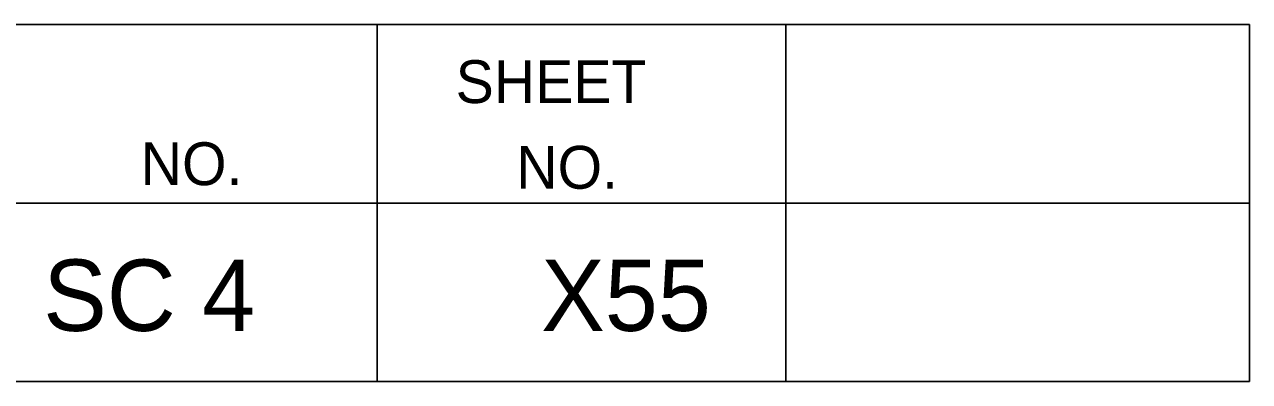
# Model space of a CAD drawing. Extents: x 1000 to 1162, y 999 to 8520.
# Drawn here: x 1152.97 to 1161.56, y 7310.05 to 7312.55 of the extents above; entities that cross this region are included whole.
import ezdxf

# ---------------------------------------------------------------- set-up
doc = ezdxf.new("R2010")
doc.units = 0
doc.layers.add('Level 20', color=7, linetype='Continuous')
doc.layers.add('Level 3', color=7, linetype='Continuous')

msp = doc.modelspace()

# ---------------------------------------------------------------- linework, layer by layer
at = {"layer": 'Level 3'}
for p, q in [((1133.055, 7312.5458), (1161.555, 7312.5458)), ((1133.055, 7312.5458), (1161.555, 7312.5458)), ((1133.055, 7312.5458), (1161.555, 7312.5458)), ((1133.055, 7312.5458), (1161.555, 7312.5458)), ((1133.055, 7312.5458), (1161.555, 7312.5458)), ((1133.055, 7312.5458), (1161.555, 7312.5458)), ((1133.055, 7312.5458), (1161.555, 7312.5458)), ((1133.055, 7312.5458), (1161.555, 7312.5458)), ((1133.055, 7312.5458), (1161.555, 7312.5458)), ((1133.055, 7312.5458), (1161.555, 7312.5458)), ((1133.055, 7312.5458), (1161.555, 7312.5458)), ((1133.055, 7312.5458), (1161.555, 7312.5458)), ((1133.055, 7312.5458), (1161.555, 7312.5458)), ((1133.055, 7312.5458), (1161.555, 7312.5458)), ((1133.055, 7312.5458), (1161.555, 7312.5458)), ((1133.055, 7312.5458), (1161.555, 7312.5458)), ((1133.055, 7312.5458), (1161.555, 7312.5458)), ((1133.055, 7312.5458), (1161.555, 7312.5458)), ((1133.055, 7312.5458), (1161.555, 7312.5458)), ((1133.055, 7312.5458), (1161.555, 7312.5458)), ((1133.055, 7312.5458), (1161.555, 7312.5458)), ((1133.055, 7312.5458), (1161.555, 7312.5458)), ((1133.055, 7312.5458), (1161.555, 7312.5458)), ((1133.055, 7312.5458), (1161.555, 7312.5458)), ((1133.055, 7312.5458), (1161.555, 7312.5458)), ((1133.055, 7312.5458), (1161.555, 7312.5458)), ((1133.055, 7312.5458), (1161.555, 7312.5458)), ((1133.055, 7312.5458), (1161.555, 7312.5458)), ((1133.055, 7312.5458), (1161.555, 7312.5458)), ((1133.055, 7312.5458), (1161.555, 7312.5458)), ((1133.055, 7312.5458), (1161.555, 7312.5458)), ((1133.055, 7312.5458), (1161.555, 7312.5458)), ((1133.055, 7312.5458), (1161.555, 7312.5458)), ((1133.055, 7312.5458), (1161.555, 7312.5458)), ((1133.055, 7312.5458), (1161.555, 7312.5458)), ((1133.055, 7312.5458), (1161.555, 7312.5458)), ((1133.055, 7312.5458), (1161.555, 7312.5458)), ((1133.055, 7312.5458), (1161.555, 7312.5458)), ((1133.055, 7312.5458), (1161.555, 7312.5458)), ((1133.055, 7312.5458), (1161.555, 7312.5458)), ((1133.055, 7312.5458), (1161.555, 7312.5458)), ((1133.055, 7312.5458), (1161.555, 7312.5458)), ((1133.055, 7312.5458), (1161.555, 7312.5458)), ((1133.055, 7312.5458), (1161.555, 7312.5458)), ((1133.055, 7312.5458), (1161.555, 7312.5458)), ((1133.055, 7312.5458), (1161.555, 7312.5458)), ((1133.055, 7312.5458), (1161.555, 7312.5458)), ((1133.055, 7312.5458), (1161.555, 7312.5458)), ((1133.055, 7312.5458), (1161.555, 7312.5458)), ((1133.055, 7312.5458), (1161.555, 7312.5458)), ((1133.055, 7312.5458), (1161.555, 7312.5458)), ((1133.055, 7312.5458), (1161.555, 7312.5458)), ((1133.055, 7312.5458), (1161.555, 7312.5458)), ((1155.44, 7312.5458), (1155.44, 7310.0458)), ((1155.44, 7312.5458), (1155.44, 7310.0458)), ((1155.44, 7312.5458), (1155.44, 7310.0458)), ((1155.44, 7312.5458), (1155.44, 7310.0458)), ((1155.44, 7312.5458), (1155.44, 7310.0458)), ((1155.44, 7312.5458), (1155.44, 7310.0458)), ((1155.44, 7312.5458), (1155.44, 7310.0458)), ((1155.44, 7312.5458), (1155.44, 7310.0458)), ((1155.44, 7312.5458), (1155.44, 7310.0458)), ((1155.44, 7312.5458), (1155.44, 7310.0458)), ((1155.44, 7312.5458), (1155.44, 7310.0458)), ((1155.44, 7312.5458), (1155.44, 7310.0458)), ((1155.44, 7312.5458), (1155.44, 7310.0458)), ((1155.44, 7312.5458), (1155.44, 7310.0458)), ((1155.44, 7312.5458), (1155.44, 7310.0458)), ((1155.44, 7312.5458), (1155.44, 7310.0458)), ((1155.44, 7312.5458), (1155.44, 7310.0458)), ((1155.44, 7312.5458), (1155.44, 7310.0458)), ((1155.44, 7312.5458), (1155.44, 7310.0458)), ((1155.44, 7312.5458), (1155.44, 7310.0458)), ((1155.44, 7312.5458), (1155.44, 7310.0458)), ((1155.44, 7312.5458), (1155.44, 7310.0458)), ((1155.44, 7312.5458), (1155.44, 7310.0458)), ((1155.44, 7312.5458), (1155.44, 7310.0458)), ((1155.44, 7312.5458), (1155.44, 7310.0458)), ((1155.44, 7312.5458), (1155.44, 7310.0458)), ((1155.44, 7312.5458), (1155.44, 7310.0458)), ((1155.44, 7312.5458), (1155.44, 7310.0458)), ((1155.44, 7312.5458), (1155.44, 7310.0458)), ((1155.44, 7312.5458), (1155.44, 7310.0458)), ((1155.44, 7312.5458), (1155.44, 7310.0458)), ((1155.44, 7312.5458), (1155.44, 7310.0458)), ((1155.44, 7312.5458), (1155.44, 7310.0458)), ((1155.44, 7312.5458), (1155.44, 7310.0458)), ((1155.44, 7312.5458), (1155.44, 7310.0458)), ((1155.44, 7312.5458), (1155.44, 7310.0458)), ((1155.44, 7312.5458), (1155.44, 7310.0458)), ((1155.44, 7312.5458), (1155.44, 7310.0458)), ((1155.44, 7312.5458), (1155.44, 7310.0458)), ((1155.44, 7312.5458), (1155.44, 7310.0458)), ((1155.44, 7312.5458), (1155.44, 7310.0458)), ((1155.44, 7312.5458), (1155.44, 7310.0458)), ((1155.44, 7312.5458), (1155.44, 7310.0458)), ((1155.44, 7312.5458), (1155.44, 7310.0458)), ((1155.44, 7312.5458), (1155.44, 7310.0458)), ((1155.44, 7312.5458), (1155.44, 7310.0458)), ((1155.44, 7312.5458), (1155.44, 7310.0458)), ((1155.44, 7312.5458), (1155.44, 7310.0458)), ((1155.44, 7312.5458), (1155.44, 7310.0458)), ((1155.44, 7312.5458), (1155.44, 7310.0458)), ((1155.44, 7312.5458), (1155.44, 7310.0458)), ((1155.44, 7312.5458), (1155.44, 7310.0458)), ((1155.44, 7312.5458), (1155.44, 7310.0458)), ((1158.305, 7312.5458), (1158.305, 7310.0458)), ((1158.305, 7312.5458), (1158.305, 7310.0458)), ((1158.305, 7312.5458), (1158.305, 7310.0458)), ((1158.305, 7312.5458), (1158.305, 7310.0458)), ((1158.305, 7312.5458), (1158.305, 7310.0458)), ((1158.305, 7312.5458), (1158.305, 7310.0458)), ((1158.305, 7312.5458), (1158.305, 7310.0458)), ((1158.305, 7312.5458), (1158.305, 7310.0458)), ((1158.305, 7312.5458), (1158.305, 7310.0458)), ((1158.305, 7312.5458), (1158.305, 7310.0458)), ((1158.305, 7312.5458), (1158.305, 7310.0458)), ((1158.305, 7312.5458), (1158.305, 7310.0458)), ((1158.305, 7312.5458), (1158.305, 7310.0458)), ((1158.305, 7312.5458), (1158.305, 7310.0458)), ((1158.305, 7312.5458), (1158.305, 7310.0458)), ((1158.305, 7312.5458), (1158.305, 7310.0458)), ((1158.305, 7312.5458), (1158.305, 7310.0458)), ((1158.305, 7312.5458), (1158.305, 7310.0458)), ((1158.305, 7312.5458), (1158.305, 7310.0458)), ((1158.305, 7312.5458), (1158.305, 7310.0458)), ((1158.305, 7312.5458), (1158.305, 7310.0458)), ((1158.305, 7312.5458), (1158.305, 7310.0458)), ((1158.305, 7312.5458), (1158.305, 7310.0458)), ((1158.305, 7312.5458), (1158.305, 7310.0458)), ((1158.305, 7312.5458), (1158.305, 7310.0458)), ((1158.305, 7312.5458), (1158.305, 7310.0458)), ((1158.305, 7312.5458), (1158.305, 7310.0458)), ((1158.305, 7312.5458), (1158.305, 7310.0458)), ((1158.305, 7312.5458), (1158.305, 7310.0458)), ((1158.305, 7312.5458), (1158.305, 7310.0458)), ((1158.305, 7312.5458), (1158.305, 7310.0458)), ((1158.305, 7312.5458), (1158.305, 7310.0458)), ((1158.305, 7312.5458), (1158.305, 7310.0458)), ((1158.305, 7312.5458), (1158.305, 7310.0458)), ((1158.305, 7312.5458), (1158.305, 7310.0458)), ((1158.305, 7312.5458), (1158.305, 7310.0458)), ((1158.305, 7312.5458), (1158.305, 7310.0458)), ((1158.305, 7312.5458), (1158.305, 7310.0458)), ((1158.305, 7312.5458), (1158.305, 7310.0458)), ((1158.305, 7312.5458), (1158.305, 7310.0458)), ((1158.305, 7312.5458), (1158.305, 7310.0458)), ((1158.305, 7312.5458), (1158.305, 7310.0458)), ((1158.305, 7312.5458), (1158.305, 7310.0458)), ((1158.305, 7312.5458), (1158.305, 7310.0458)), ((1158.305, 7312.5458), (1158.305, 7310.0458)), ((1158.305, 7312.5458), (1158.305, 7310.0458)), ((1158.305, 7312.5458), (1158.305, 7310.0458)), ((1158.305, 7312.5458), (1158.305, 7310.0458)), ((1158.305, 7312.5458), (1158.305, 7310.0458)), ((1158.305, 7312.5458), (1158.305, 7310.0458)), ((1158.305, 7312.5458), (1158.305, 7310.0458)), ((1158.305, 7312.5458), (1158.305, 7310.0458)), ((1158.305, 7312.5458), (1158.305, 7310.0458)), ((1161.555, 7312.5458), (1161.555, 7310.0458)), ((1161.555, 7312.5458), (1161.555, 7310.0458)), ((1161.555, 7312.5458), (1161.555, 7310.0458)), ((1161.555, 7312.5458), (1161.555, 7310.0458)), ((1161.555, 7312.5458), (1161.555, 7310.0458)), ((1161.555, 7312.5458), (1161.555, 7310.0458)), ((1161.555, 7312.5458), (1161.555, 7310.0458)), ((1161.555, 7312.5458), (1161.555, 7310.0458)), ((1161.555, 7312.5458), (1161.555, 7310.0458)), ((1161.555, 7312.5458), (1161.555, 7310.0458)), ((1161.555, 7312.5458), (1161.555, 7310.0458)), ((1161.555, 7312.5458), (1161.555, 7310.0458)), ((1161.555, 7312.5458), (1161.555, 7310.0458)), ((1161.555, 7312.5458), (1161.555, 7310.0458)), ((1161.555, 7312.5458), (1161.555, 7310.0458)), ((1161.555, 7312.5458), (1161.555, 7310.0458)), ((1161.555, 7312.5458), (1161.555, 7310.0458)), ((1161.555, 7312.5458), (1161.555, 7310.0458)), ((1161.555, 7312.5458), (1161.555, 7310.0458)), ((1161.555, 7312.5458), (1161.555, 7310.0458)), ((1161.555, 7312.5458), (1161.555, 7310.0458)), ((1161.555, 7312.5458), (1161.555, 7310.0458)), ((1161.555, 7312.5458), (1161.555, 7310.0458)), ((1161.555, 7312.5458), (1161.555, 7310.0458)), ((1161.555, 7312.5458), (1161.555, 7310.0458)), ((1161.555, 7312.5458), (1161.555, 7310.0458)), ((1161.555, 7312.5458), (1161.555, 7310.0458)), ((1161.555, 7312.5458), (1161.555, 7310.0458)), ((1161.555, 7312.5458), (1161.555, 7310.0458)), ((1161.555, 7312.5458), (1161.555, 7310.0458)), ((1161.555, 7312.5458), (1161.555, 7310.0458)), ((1161.555, 7312.5458), (1161.555, 7310.0458)), ((1161.555, 7312.5458), (1161.555, 7310.0458)), ((1161.555, 7312.5458), (1161.555, 7310.0458)), ((1161.555, 7312.5458), (1161.555, 7310.0458)), ((1161.555, 7312.5458), (1161.555, 7310.0458)), ((1161.555, 7312.5458), (1161.555, 7310.0458)), ((1161.555, 7312.5458), (1161.555, 7310.0458)), ((1161.555, 7312.5458), (1161.555, 7310.0458)), ((1161.555, 7312.5458), (1161.555, 7310.0458)), ((1161.555, 7312.5458), (1161.555, 7310.0458)), ((1161.555, 7312.5458), (1161.555, 7310.0458)), ((1161.555, 7312.5458), (1161.555, 7310.0458)), ((1161.555, 7312.5458), (1161.555, 7310.0458)), ((1161.555, 7312.5458), (1161.555, 7310.0458)), ((1161.555, 7312.5458), (1161.555, 7310.0458)), ((1161.555, 7312.5458), (1161.555, 7310.0458)), ((1161.555, 7312.5458), (1161.555, 7310.0458)), ((1161.555, 7312.5458), (1161.555, 7310.0458)), ((1161.555, 7312.5458), (1161.555, 7310.0458)), ((1161.555, 7312.5458), (1161.555, 7310.0458)), ((1161.555, 7312.5458), (1161.555, 7310.0458)), ((1161.555, 7312.5458), (1161.555, 7310.0458)), ((1133.055, 7311.2958), (1161.555, 7311.2958)), ((1133.055, 7311.2958), (1161.555, 7311.2958)), ((1133.055, 7311.2958), (1161.555, 7311.2958)), ((1133.055, 7311.2958), (1161.555, 7311.2958)), ((1133.055, 7311.2958), (1161.555, 7311.2958)), ((1133.055, 7311.2958), (1161.555, 7311.2958)), ((1133.055, 7311.2958), (1161.555, 7311.2958)), ((1133.055, 7311.2958), (1161.555, 7311.2958)), ((1133.055, 7311.2958), (1161.555, 7311.2958)), ((1133.055, 7311.2958), (1161.555, 7311.2958)), ((1133.055, 7311.2958), (1161.555, 7311.2958)), ((1133.055, 7311.2958), (1161.555, 7311.2958)), ((1133.055, 7311.2958), (1161.555, 7311.2958)), ((1133.055, 7311.2958), (1161.555, 7311.2958)), ((1133.055, 7311.2958), (1161.555, 7311.2958)), ((1133.055, 7311.2958), (1161.555, 7311.2958)), ((1133.055, 7311.2958), (1161.555, 7311.2958)), ((1133.055, 7311.2958), (1161.555, 7311.2958)), ((1133.055, 7311.2958), (1161.555, 7311.2958)), ((1133.055, 7311.2958), (1161.555, 7311.2958)), ((1133.055, 7311.2958), (1161.555, 7311.2958)), ((1133.055, 7311.2958), (1161.555, 7311.2958)), ((1133.055, 7311.2958), (1161.555, 7311.2958)), ((1133.055, 7311.2958), (1161.555, 7311.2958)), ((1133.055, 7311.2958), (1161.555, 7311.2958)), ((1133.055, 7311.2958), (1161.555, 7311.2958)), ((1133.055, 7311.2958), (1161.555, 7311.2958)), ((1133.055, 7311.2958), (1161.555, 7311.2958)), ((1133.055, 7311.2958), (1161.555, 7311.2958)), ((1133.055, 7311.2958), (1161.555, 7311.2958)), ((1133.055, 7311.2958), (1161.555, 7311.2958)), ((1133.055, 7311.2958), (1161.555, 7311.2958)), ((1133.055, 7311.2958), (1161.555, 7311.2958)), ((1133.055, 7311.2958), (1161.555, 7311.2958)), ((1133.055, 7311.2958), (1161.555, 7311.2958)), ((1133.055, 7311.2958), (1161.555, 7311.2958)), ((1133.055, 7311.2958), (1161.555, 7311.2958)), ((1133.055, 7311.2958), (1161.555, 7311.2958)), ((1133.055, 7311.2958), (1161.555, 7311.2958)), ((1133.055, 7311.2958), (1161.555, 7311.2958)), ((1133.055, 7311.2958), (1161.555, 7311.2958)), ((1133.055, 7311.2958), (1161.555, 7311.2958)), ((1133.055, 7311.2958), (1161.555, 7311.2958)), ((1133.055, 7311.2958), (1161.555, 7311.2958)), ((1133.055, 7311.2958), (1161.555, 7311.2958)), ((1133.055, 7311.2958), (1161.555, 7311.2958)), ((1133.055, 7311.2958), (1161.555, 7311.2958)), ((1133.055, 7311.2958), (1161.555, 7311.2958)), ((1133.055, 7311.2958), (1161.555, 7311.2958)), ((1133.055, 7311.2958), (1161.555, 7311.2958)), ((1133.055, 7311.2958), (1161.555, 7311.2958)), ((1133.055, 7311.2958), (1161.555, 7311.2958)), ((1133.055, 7311.2958), (1161.555, 7311.2958)), ((1133.055, 7310.0458), (1161.555, 7310.0458)), ((1133.055, 7310.0458), (1161.555, 7310.0458)), ((1133.055, 7310.0458), (1161.555, 7310.0458)), ((1133.055, 7310.0458), (1161.555, 7310.0458)), ((1133.055, 7310.0458), (1161.555, 7310.0458)), ((1133.055, 7310.0458), (1161.555, 7310.0458)), ((1133.055, 7310.0458), (1161.555, 7310.0458)), ((1133.055, 7310.0458), (1161.555, 7310.0458)), ((1133.055, 7310.0458), (1161.555, 7310.0458)), ((1133.055, 7310.0458), (1161.555, 7310.0458)), ((1133.055, 7310.0458), (1161.555, 7310.0458)), ((1133.055, 7310.0458), (1161.555, 7310.0458)), ((1133.055, 7310.0458), (1161.555, 7310.0458)), ((1133.055, 7310.0458), (1161.555, 7310.0458)), ((1133.055, 7310.0458), (1161.555, 7310.0458)), ((1133.055, 7310.0458), (1161.555, 7310.0458)), ((1133.055, 7310.0458), (1161.555, 7310.0458)), ((1133.055, 7310.0458), (1161.555, 7310.0458)), ((1133.055, 7310.0458), (1161.555, 7310.0458)), ((1133.055, 7310.0458), (1161.555, 7310.0458)), ((1133.055, 7310.0458), (1161.555, 7310.0458)), ((1133.055, 7310.0458), (1161.555, 7310.0458)), ((1133.055, 7310.0458), (1161.555, 7310.0458)), ((1133.055, 7310.0458), (1161.555, 7310.0458)), ((1133.055, 7310.0458), (1161.555, 7310.0458)), ((1133.055, 7310.0458), (1161.555, 7310.0458)), ((1133.055, 7310.0458), (1161.555, 7310.0458)), ((1133.055, 7310.0458), (1161.555, 7310.0458)), ((1133.055, 7310.0458), (1161.555, 7310.0458)), ((1133.055, 7310.0458), (1161.555, 7310.0458)), ((1133.055, 7310.0458), (1161.555, 7310.0458)), ((1133.055, 7310.0458), (1161.555, 7310.0458)), ((1133.055, 7310.0458), (1161.555, 7310.0458)), ((1133.055, 7310.0458), (1161.555, 7310.0458)), ((1133.055, 7310.0458), (1161.555, 7310.0458)), ((1133.055, 7310.0458), (1161.555, 7310.0458)), ((1133.055, 7310.0458), (1161.555, 7310.0458)), ((1133.055, 7310.0458), (1161.555, 7310.0458)), ((1133.055, 7310.0458), (1161.555, 7310.0458)), ((1133.055, 7310.0458), (1161.555, 7310.0458)), ((1133.055, 7310.0458), (1161.555, 7310.0458)), ((1133.055, 7310.0458), (1161.555, 7310.0458)), ((1133.055, 7310.0458), (1161.555, 7310.0458)), ((1133.055, 7310.0458), (1161.555, 7310.0458)), ((1133.055, 7310.0458), (1161.555, 7310.0458)), ((1133.055, 7310.0458), (1161.555, 7310.0458)), ((1133.055, 7310.0458), (1161.555, 7310.0458)), ((1133.055, 7310.0458), (1161.555, 7310.0458)), ((1133.055, 7310.0458), (1161.555, 7310.0458)), ((1133.055, 7310.0458), (1161.555, 7310.0458)), ((1133.055, 7310.0458), (1161.555, 7310.0458)), ((1133.055, 7310.0458), (1161.555, 7310.0458)), ((1133.055, 7310.0458), (1161.555, 7310.0458))]:
    msp.add_line(p, q, dxfattribs=at)

# ---------------------------------------------------------------- texts
at = {"layer": 'Level 20'}
for s, p in [('SC 4', (1153.0988, 7310.4)), ('X55', (1156.5896, 7310.4))]:
    msp.add_text(s, height=0.5, dxfattribs=at).set_placement(p)
at = {"layer": 'Level 3'}
for s, p in [('SHEET', (1155.99, 7311.9958)), ('SHEET', (1155.99, 7311.9958)), ('SHEET', (1155.99, 7311.9958)), ('SHEET', (1155.99, 7311.9958)), ('SHEET', (1155.99, 7311.9958)), ('SHEET', (1155.99, 7311.9958)), ('SHEET', (1155.99, 7311.9958)), ('SHEET', (1155.99, 7311.9958)), ('SHEET', (1155.99, 7311.9958)), ('SHEET', (1155.99, 7311.9958)), ('SHEET', (1155.99, 7311.9958)), ('SHEET', (1155.99, 7311.9958)), ('SHEET', (1155.99, 7311.9958)), ('SHEET', (1155.99, 7311.9958)), ('SHEET', (1155.99, 7311.9958)), ('SHEET', (1155.99, 7311.9958)), ('SHEET', (1155.99, 7311.9958)), ('SHEET', (1155.99, 7311.9958)), ('SHEET', (1155.99, 7311.9958)), ('SHEET', (1155.99, 7311.9958)), ('SHEET', (1155.99, 7311.9958)), ('SHEET', (1155.99, 7311.9958)), ('SHEET', (1155.99, 7311.9958)), ('SHEET', (1155.99, 7311.9958)), ('SHEET', (1155.99, 7311.9958)), ('SHEET', (1155.99, 7311.9958)), ('SHEET', (1155.99, 7311.9958)), ('SHEET', (1155.99, 7311.9958)), ('SHEET', (1155.99, 7311.9958)), ('SHEET', (1155.99, 7311.9958)), ('SHEET', (1155.99, 7311.9958)), ('SHEET', (1155.99, 7311.9958)), ('SHEET', (1155.99, 7311.9958)), ('SHEET', (1155.99, 7311.9958)), ('SHEET', (1155.99, 7311.9958)), ('SHEET', (1155.99, 7311.9958)), ('SHEET', (1155.99, 7311.9958)), ('SHEET', (1155.99, 7311.9958)), ('SHEET', (1155.99, 7311.9958)), ('SHEET', (1155.99, 7311.9958)), ('SHEET', (1155.99, 7311.9958)), ('SHEET', (1155.99, 7311.9958)), ('SHEET', (1155.99, 7311.9958)), ('SHEET', (1155.99, 7311.9958)), ('SHEET', (1155.99, 7311.9958)), ('SHEET', (1155.99, 7311.9958)), ('SHEET', (1155.99, 7311.9958)), ('SHEET', (1155.99, 7311.9958)), ('SHEET', (1155.99, 7311.9958)), ('SHEET', (1155.99, 7311.9958)), ('SHEET', (1155.99, 7311.9958)), ('SHEET', (1155.99, 7311.9958)), ('SHEET', (1155.99, 7311.9958)), ('NO.', (1153.7822, 7311.4208)), ('NO.', (1153.7822, 7311.4208)), ('NO.', (1153.7822, 7311.4208)), ('NO.', (1153.7822, 7311.4208)), ('NO.', (1153.7822, 7311.4208)), ('NO.', (1153.7822, 7311.4208)), ('NO.', (1153.7822, 7311.4208)), ('NO.', (1153.7822, 7311.4208)), ('NO.', (1153.7822, 7311.4208)), ('NO.', (1153.7822, 7311.4208)), ('NO.', (1153.7822, 7311.4208)), ('NO.', (1153.7822, 7311.4208)), ('NO.', (1153.7822, 7311.4208)), ('NO.', (1153.7822, 7311.4208)), ('NO.', (1153.7822, 7311.4208)), ('NO.', (1153.7822, 7311.4208)), ('NO.', (1153.7822, 7311.4208)), ('NO.', (1153.7822, 7311.4208)), ('NO.', (1153.7822, 7311.4208)), ('NO.', (1153.7822, 7311.4208)), ('NO.', (1153.7822, 7311.4208)), ('NO.', (1153.7822, 7311.4208)), ('NO.', (1153.7822, 7311.4208)), ('NO.', (1153.7822, 7311.4208)), ('NO.', (1153.7822, 7311.4208)), ('NO.', (1153.7822, 7311.4208)), ('NO.', (1153.7822, 7311.4208)), ('NO.', (1153.7822, 7311.4208)), ('NO.', (1153.7822, 7311.4208)), ('NO.', (1153.7822, 7311.4208)), ('NO.', (1153.7822, 7311.4208)), ('NO.', (1153.7822, 7311.4208)), ('NO.', (1153.7822, 7311.4208)), ('NO.', (1153.7822, 7311.4208)), ('NO.', (1153.7822, 7311.4208)), ('NO.', (1153.7822, 7311.4208)), ('NO.', (1153.7822, 7311.4208)), ('NO.', (1153.7822, 7311.4208)), ('NO.', (1153.7822, 7311.4208)), ('NO.', (1153.7822, 7311.4208)), ('NO.', (1153.7822, 7311.4208)), ('NO.', (1153.7822, 7311.4208)), ('NO.', (1153.7822, 7311.4208)), ('NO.', (1153.7822, 7311.4208)), ('NO.', (1153.7822, 7311.4208)), ('NO.', (1153.7822, 7311.4208)), ('NO.', (1153.7822, 7311.4208)), ('NO.', (1153.7822, 7311.4208)), ('NO.', (1153.7822, 7311.4208)), ('NO.', (1153.7822, 7311.4208)), ('NO.', (1153.7822, 7311.4208)), ('NO.', (1153.7822, 7311.4208)), ('NO.', (1153.7822, 7311.4208)), ('NO.', (1156.415, 7311.3958)), ('NO.', (1156.415, 7311.3958)), ('NO.', (1156.415, 7311.3958)), ('NO.', (1156.415, 7311.3958)), ('NO.', (1156.415, 7311.3958)), ('NO.', (1156.415, 7311.3958)), ('NO.', (1156.415, 7311.3958)), ('NO.', (1156.415, 7311.3958)), ('NO.', (1156.415, 7311.3958)), ('NO.', (1156.415, 7311.3958)), ('NO.', (1156.415, 7311.3958)), ('NO.', (1156.415, 7311.3958)), ('NO.', (1156.415, 7311.3958)), ('NO.', (1156.415, 7311.3958)), ('NO.', (1156.415, 7311.3958)), ('NO.', (1156.415, 7311.3958)), ('NO.', (1156.415, 7311.3958)), ('NO.', (1156.415, 7311.3958)), ('NO.', (1156.415, 7311.3958)), ('NO.', (1156.415, 7311.3958)), ('NO.', (1156.415, 7311.3958)), ('NO.', (1156.415, 7311.3958)), ('NO.', (1156.415, 7311.3958)), ('NO.', (1156.415, 7311.3958)), ('NO.', (1156.415, 7311.3958)), ('NO.', (1156.415, 7311.3958)), ('NO.', (1156.415, 7311.3958)), ('NO.', (1156.415, 7311.3958)), ('NO.', (1156.415, 7311.3958)), ('NO.', (1156.415, 7311.3958)), ('NO.', (1156.415, 7311.3958)), ('NO.', (1156.415, 7311.3958)), ('NO.', (1156.415, 7311.3958)), ('NO.', (1156.415, 7311.3958)), ('NO.', (1156.415, 7311.3958)), ('NO.', (1156.415, 7311.3958)), ('NO.', (1156.415, 7311.3958)), ('NO.', (1156.415, 7311.3958)), ('NO.', (1156.415, 7311.3958)), ('NO.', (1156.415, 7311.3958)), ('NO.', (1156.415, 7311.3958)), ('NO.', (1156.415, 7311.3958)), ('NO.', (1156.415, 7311.3958)), ('NO.', (1156.415, 7311.3958)), ('NO.', (1156.415, 7311.3958)), ('NO.', (1156.415, 7311.3958)), ('NO.', (1156.415, 7311.3958)), ('NO.', (1156.415, 7311.3958)), ('NO.', (1156.415, 7311.3958)), ('NO.', (1156.415, 7311.3958)), ('NO.', (1156.415, 7311.3958)), ('NO.', (1156.415, 7311.3958)), ('NO.', (1156.415, 7311.3958))]:
    msp.add_text(s, height=0.3, dxfattribs=at).set_placement(p)

doc.saveas('drawing.dxf')
